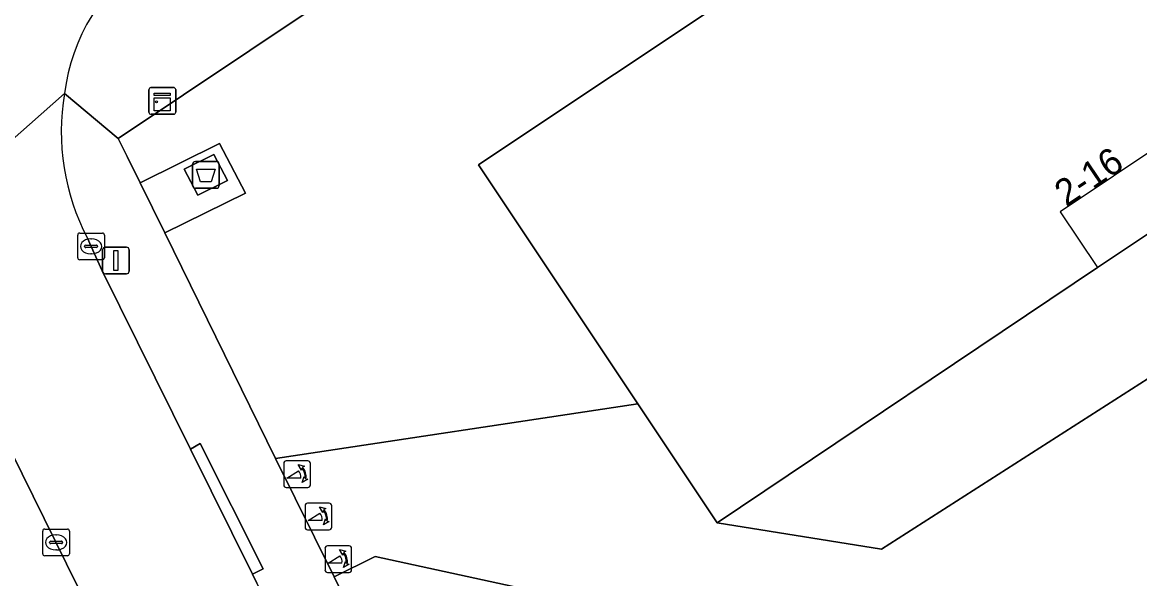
# Model space of a CAD drawing. Extents: x 161347 to 161881, y 382161 to 382804.
# Drawn here: x 161431.99 to 161473.77, y 382484.21 to 382505.01 of the extents above; entities that cross this region are included whole.
import ezdxf

# ---------------------------------------------------------------- set-up
doc = ezdxf.new("R2010")
doc.units = 0
for name, color, linetype in [('IMGEO_Afval_apart_plaats', 7, 'Continuous'), ('IMGEO_Erf', 7, 'Continuous'), ('IMGEO_Groenvoorziening', 7, 'Continuous'), ('IMGEO_Kast', 7, 'Continuous'), ('IMGEO_Kolk', 7, 'Continuous'), ('IMGEO_Lichtmast', 7, 'Continuous'), ('IMGEO_Pand', 7, 'Continuous'), ('IMGEO_Pand_nummerreeks', 7, 'Continuous'), ('IMGEO_Pand_overbouw', 7, 'Continuous'), ('IMGEO_Poller', 7, 'Continuous'), ('IMGEO_Rijbaan_lokaal_open', 7, 'Continuous'), ('IMGEO_Voetpad_gesloten', 7, 'Continuous'), ('IMGEO_Voetpad_open', 7, 'Continuous')]:
    doc.layers.add(name, color=color, linetype=linetype)

msp = doc.modelspace()

# ---------------------------------------------------------------- linework, layer by layer
at = {"layer": 'IMGEO_Afval_apart_plaats'}
for p, q in [((161438.356, 382498.913), (161438.356, 382499.713)), ((161438.356, 382499.713), (161438.356, 382498.913)), ((161438.456, 382499.813), (161439.246, 382499.813)), ((161439.246, 382499.813), (161438.456, 382499.813)), ((161439.346, 382499.713), (161439.346, 382498.913)), ((161439.346, 382498.913), (161439.346, 382499.713)), ((161439.246, 382498.813), (161438.456, 382498.813)), ((161438.456, 382498.813), (161439.246, 382498.813))]:
    msp.add_line(p, q, dxfattribs=at)
msp.add_lwpolyline([(161438.499, 382499.527), (161439.203, 382499.527), (161439.054, 382499.057), (161438.648, 382499.057), (161438.499, 382499.527)], dxfattribs=at)
for centre, start, end in [((161438.456, 382499.713), 90, 180), ((161438.456, 382499.713), 90, 180), ((161439.246, 382499.713), 0, 90), ((161439.246, 382499.713), 360, 90), ((161438.456, 382498.913), 180, 270), ((161438.456, 382498.913), 180, 270), ((161439.246, 382498.913), 270, 0), ((161439.246, 382498.913), 270, 0)]:
    msp.add_arc(centre, 0.1, start, end, dxfattribs=at)
at = {"layer": 'IMGEO_Erf'}
for points in [[(161490.393, 382508.028), (161478.402, 382500), (161475.671, 382498.172), (161472.197, 382495.844), (161457.968, 382486.306), (161464.119, 382485.318), (161475.341, 382492.496), (161486.569, 382500), (161491.524, 382503.311), (161494.163, 382503.857), (161500, 382502.6), (161512.072, 382500), (161520.272, 382498.234), (161522.532, 382496.667), (161539.309, 382469.447), (161545.974, 382467.342), (161536.968, 382481.919), (161534.501, 382485.913), (161525.798, 382500), (161525.522, 382500.446), (161522.985, 382502.254), (161514.037, 382504.398), (161513.736, 382503.008), (161502.162, 382505.515)], [(161529.133, 382472.859), (161500, 382479.131), (161475.815, 382484.338), (161475.174, 382481.282), (161481.945, 382479.796), (161482.684, 382479.645), (161485.462, 382479.04), (161497.294, 382476.49), (161493.615, 382459.469), (161478.517, 382462.719), (161477.639, 382458.64), (161456.073, 382463.283), (161459.231, 382477.951), (161480.549, 382473.354), (161481.379, 382477.176), (161445.186, 382485.044), (161443.651, 382484.283), (161457.359, 382456.669), (161460.674, 382449.996)]]:
    msp.add_lwpolyline(points, dxfattribs=at)
at = {"layer": 'IMGEO_Groenvoorziening'}
msp.add_lwpolyline([(161489.707, 382536.855), (161435.571, 382500.672), (161435.902, 382500), (161436.388, 382499.018), (161439.358, 382500.48), (161440.335, 382498.631), (161437.311, 382497.143), (161441.46, 382488.708), (161455.008, 382490.746), (161449.044, 382499.691), (161449.506, 382500), (161463.38, 382509.249)], dxfattribs=at)
at = {"layer": 'IMGEO_Kast'}
for p, q in [((161436.796, 382502.577), (161437.637, 382502.577)), ((161437.637, 382502.577), (161436.796, 382502.577)), ((161436.721, 382501.652), (161436.721, 382502.493)), ((161436.721, 382502.493), (161436.721, 382501.652)), ((161437.721, 382502.502), (161437.721, 382501.661)), ((161437.721, 382501.661), (161437.721, 382502.502)), ((161437.646, 382501.577), (161436.805, 382501.577)), ((161436.805, 382501.577), (161437.646, 382501.577))]:
    msp.add_line(p, q, dxfattribs=at)
for points in [[(161436.916, 382502.367), (161437.516, 382502.367), (161437.516, 382502.282), (161436.916, 382502.282), (161436.916, 382502.367)], [(161436.916, 382502.192), (161437.516, 382502.192), (161437.516, 382501.703), (161436.916, 382501.703), (161436.916, 382502.192)]]:
    msp.add_lwpolyline(points, dxfattribs=at)
msp.add_circle((161437, 382502.041), 0.0377, dxfattribs=at)
for centre, start, end in [((161436.799, 382502.499), 92.4484, 184.2845), ((161436.799, 382502.499), 92.4484, 184.2845), ((161437.643, 382502.499), 2.4484, 94.2845), ((161437.643, 382502.499), 2.4484, 94.2845), ((161436.799, 382501.655), 182.4484, 274.2845), ((161436.799, 382501.655), 182.4484, 274.2845), ((161437.643, 382501.655), 272.4484, 4.2845), ((161437.643, 382501.655), 272.4484, 4.2845)]:
    msp.add_arc(centre, 0.0779, start, end, dxfattribs=at)
at = {"layer": 'IMGEO_Kolk'}
for p, q in [((161434.131, 382497.137), (161434.983, 382497.137)), ((161434.056, 382496.211), (161434.056, 382497.063)), ((161434.358, 382496.68), (161434.756, 382496.68)), ((161434.544, 382496.917), (161434.569, 382496.917)), ((161435.057, 382497.063), (161435.057, 382496.211)), ((161434.315, 382496.631), (161434.315, 382496.643)), ((161434.753, 382496.594), (161434.355, 382496.594)), ((161434.567, 382496.357), (161434.542, 382496.357)), ((161434.799, 382496.643), (161434.799, 382496.631)), ((161434.983, 382496.137), (161434.131, 382496.137)), ((161432.748, 382485.142), (161432.748, 382485.994)), ((161432.823, 382486.068), (161433.675, 382486.068)), ((161433.236, 382485.848), (161433.261, 382485.848)), ((161433.749, 382485.994), (161433.749, 382485.142)), ((161433.007, 382485.562), (161433.007, 382485.574)), ((161433.445, 382485.525), (161433.047, 382485.525)), ((161433.05, 382485.611), (161433.448, 382485.611)), ((161433.491, 382485.574), (161433.491, 382485.562)), ((161433.675, 382485.068), (161432.823, 382485.068)), ((161433.259, 382485.288), (161433.234, 382485.288))]:
    msp.add_line(p, q, dxfattribs=at)
for points in [[(161434.131, 382497.137), (161434.983, 382497.137)], [(161434.056, 382496.211), (161434.056, 382497.063)], [(161435.057, 382497.063), (161435.057, 382496.211)], [(161434.983, 382496.137), (161434.131, 382496.137)], [(161432.748, 382485.142), (161432.748, 382485.994)], [(161432.823, 382486.068), (161433.675, 382486.068)], [(161433.749, 382485.994), (161433.749, 382485.142)], [(161433.675, 382485.068), (161432.823, 382485.068)]]:
    msp.add_lwpolyline(points, dxfattribs=at)
for centre, radius, start, end in [((161434.133, 382497.061), 0.0765, 91.552, 178.448), ((161434.133, 382497.061), 0.0765, 91.552, 178.448), ((161434.981, 382497.061), 0.0765, 1.552, 88.448), ((161434.981, 382497.061), 0.0765, 1.552, 88.448), ((161434.355, 382496.64), 0.0403, 85.8775, 175.7526), ((161434.76, 382496.642), 0.0386, 1.7309, 96.639), ((161434.352, 382496.63), 0.0366, 178.938, 274.7102), ((161434.756, 382496.637), 0.043, 264.8664, 352.4533), ((161434.133, 382496.213), 0.0765, 181.552, 268.448), ((161434.133, 382496.213), 0.0765, 181.552, 268.448), ((161434.981, 382496.213), 0.0765, 271.552, 358.448), ((161434.981, 382496.213), 0.0765, 271.552, 358.448), ((161432.825, 382485.992), 0.0765, 91.552, 178.448), ((161432.825, 382485.992), 0.0765, 91.552, 178.448), ((161433.673, 382485.992), 0.0765, 1.552, 88.448), ((161433.673, 382485.992), 0.0765, 1.552, 88.448), ((161433.047, 382485.571), 0.0403, 85.8775, 175.7526), ((161433.044, 382485.561), 0.0366, 178.938, 274.7102), ((161433.448, 382485.568), 0.043, 264.8664, 352.4533), ((161433.452, 382485.573), 0.0386, 1.7309, 96.639), ((161432.825, 382485.144), 0.0765, 181.552, 268.448), ((161432.825, 382485.144), 0.0765, 181.552, 268.448), ((161433.673, 382485.144), 0.0765, 271.552, 358.448), ((161433.673, 382485.144), 0.0765, 271.552, 358.448)]:
    msp.add_arc(centre, radius, start, end, dxfattribs=at)
for centre, major_axis, ratio, start_param, end_param in [((161434.543, 382496.637), (-0.387, 0.002), 0.722429, 4.712389, 7.853982), ((161434.568, 382496.637), (-0.39, 0.002), 0.717154, 1.570796, 4.712389), ((161433.235, 382485.568), (-0.387, 0.002), 0.722429, 4.712389, 7.853982), ((161433.26, 382485.568), (-0.39, 0.002), 0.717154, 1.570796, 4.712389)]:
    msp.add_ellipse(centre, major_axis=major_axis, ratio=ratio, start_param=start_param, end_param=end_param, dxfattribs=at)
at = {"layer": 'IMGEO_Lichtmast'}
for p, q in [((161434.99, 382495.71), (161434.99, 382496.51)), ((161434.99, 382496.51), (161434.99, 382495.71)), ((161435.09, 382496.61), (161435.88, 382496.61)), ((161435.88, 382496.61), (161435.09, 382496.61)), ((161435.98, 382496.51), (161435.98, 382495.71)), ((161435.98, 382495.71), (161435.98, 382496.51)), ((161435.88, 382495.61), (161435.09, 382495.61)), ((161435.09, 382495.61), (161435.88, 382495.61))]:
    msp.add_line(p, q, dxfattribs=at)
msp.add_lwpolyline([(161435.41, 382496.485), (161435.56, 382496.485), (161435.56, 382495.735), (161435.41, 382495.735), (161435.41, 382496.485)], dxfattribs=at)
for centre, start, end in [((161435.09, 382496.51), 90, 180), ((161435.09, 382496.51), 90, 180), ((161435.88, 382496.51), 0, 90), ((161435.88, 382496.51), 360, 90), ((161435.09, 382495.71), 180, 270), ((161435.09, 382495.71), 180, 270), ((161435.88, 382495.71), 270, 0), ((161435.88, 382495.71), 270, 0)]:
    msp.add_arc(centre, 0.1, start, end, dxfattribs=at)
at = {"layer": 'IMGEO_Pand'}
msp.add_lwpolyline([(161463.38, 382509.249), (161449.506, 382500), (161449.044, 382499.691), (161455.008, 382490.746), (161457.968, 382486.306), (161472.197, 382495.844), (161475.671, 382498.172), (161478.402, 382500), (161490.393, 382508.028)], dxfattribs=at)
at = {"layer": 'IMGEO_Pand_overbouw'}
msp.add_lwpolyline([(161474.826, 382500.62), (161470.803, 382497.924), (161472.197, 382495.844), (161475.671, 382498.172), (161476.221, 382498.54)], close=True, dxfattribs=at)
at = {"layer": 'IMGEO_Poller'}
for p, q in [((161441.762, 382488.525), (161441.762, 382487.718)), ((161441.762, 382488.525), (161441.762, 382487.718)), ((161442.664, 382488.62), (161441.856, 382488.62)), ((161442.664, 382488.62), (161441.856, 382488.62)), ((161442.758, 382487.718), (161442.758, 382488.525)), ((161442.758, 382487.718), (161442.758, 382488.525)), ((161441.856, 382487.623), (161442.664, 382487.623)), ((161441.856, 382487.623), (161442.664, 382487.623)), ((161442.56, 382486.942), (161442.56, 382486.135)), ((161442.56, 382486.942), (161442.56, 382486.135)), ((161443.462, 382487.037), (161442.654, 382487.037)), ((161443.462, 382487.037), (161442.654, 382487.037)), ((161443.556, 382486.135), (161443.556, 382486.942)), ((161443.556, 382486.135), (161443.556, 382486.942)), ((161442.654, 382486.04), (161443.462, 382486.04)), ((161442.654, 382486.04), (161443.462, 382486.04)), ((161444.208, 382485.441), (161443.4, 382485.441)), ((161444.208, 382485.441), (161443.4, 382485.441)), ((161443.306, 382485.346), (161443.306, 382484.539)), ((161443.306, 382485.346), (161443.306, 382484.539)), ((161444.302, 382484.539), (161444.302, 382485.346)), ((161444.302, 382484.539), (161444.302, 382485.346)), ((161443.4, 382484.444), (161444.208, 382484.444)), ((161443.4, 382484.444), (161444.208, 382484.444))]:
    msp.add_line(p, q, dxfattribs=at)
for points in [[(161442.441, 382488.349), (161442.429, 382488.276), (161442.304, 382488.481)], [(161442.304, 382488.481), (161442.535, 382488.415), (161442.464, 382488.383)], [(161442.397, 382487.976), (161441.884, 382487.976), (161442.314, 382488.251)], [(161442.457, 382487.804), (161442.523, 382488.035), (161442.553, 382487.967)], [(161442.589, 382487.94), (161442.661, 382487.929), (161442.457, 382487.804)], [(161443.195, 382486.393), (161442.682, 382486.393), (161443.112, 382486.668)], [(161443.239, 382486.766), (161443.227, 382486.693), (161443.102, 382486.898)], [(161443.102, 382486.898), (161443.333, 382486.832), (161443.262, 382486.8)], [(161443.255, 382486.221), (161443.321, 382486.452), (161443.351, 382486.384)], [(161443.387, 382486.357), (161443.459, 382486.346), (161443.255, 382486.221)], [(161443.941, 382484.797), (161443.428, 382484.797), (161443.858, 382485.072)], [(161443.985, 382485.17), (161443.973, 382485.097), (161443.848, 382485.302)], [(161443.848, 382485.302), (161444.079, 382485.236), (161444.008, 382485.204)], [(161444.001, 382484.625), (161444.067, 382484.856), (161444.097, 382484.788)], [(161444.133, 382484.761), (161444.205, 382484.75), (161444.001, 382484.625)]]:
    msp.add_lwpolyline(points, dxfattribs=at)
for centre, radius, start, end in [((161441.856, 382488.525), 0.0946, 90, 180), ((161441.856, 382488.525), 0.0946, 90, 180), ((161442.083, 382488.036), 0.476, 351.7527, 41.1691), ((161442.083, 382488.036), 0.516, 349.3569, 42.2912), ((161442.664, 382488.525), 0.0946, 0, 90), ((161442.664, 382488.525), 0.0946, 0, 90), ((161442.069, 382488.026), 0.332, 351.3247, 42.4854), ((161441.856, 382487.718), 0.0946, 180, 270), ((161441.856, 382487.718), 0.0946, 180, 270), ((161442.664, 382487.718), 0.0946, 270, 0), ((161442.664, 382487.718), 0.0946, 270, 0), ((161442.654, 382486.942), 0.0946, 90, 180), ((161442.654, 382486.942), 0.0946, 90, 180), ((161442.867, 382486.443), 0.332, 351.3247, 42.4854), ((161442.881, 382486.453), 0.476, 351.7527, 41.1691), ((161442.881, 382486.453), 0.516, 349.3569, 42.2912), ((161443.462, 382486.942), 0.0946, 0, 90), ((161443.462, 382486.942), 0.0946, 0, 90), ((161442.654, 382486.135), 0.0946, 180, 270), ((161442.654, 382486.135), 0.0946, 180, 270), ((161443.462, 382486.135), 0.0946, 270, 0), ((161443.462, 382486.135), 0.0946, 270, 0), ((161443.4, 382485.346), 0.0946, 90, 180), ((161443.4, 382485.346), 0.0946, 90, 180), ((161444.208, 382485.346), 0.0946, 0, 90), ((161444.208, 382485.346), 0.0946, 0, 90), ((161443.613, 382484.847), 0.332, 351.3247, 42.4854), ((161443.627, 382484.857), 0.476, 351.7527, 41.1691), ((161443.627, 382484.857), 0.516, 349.3569, 42.2912), ((161443.4, 382484.539), 0.0946, 180, 270), ((161443.4, 382484.539), 0.0946, 180, 270), ((161444.208, 382484.539), 0.0946, 270, 0), ((161444.208, 382484.539), 0.0946, 270, 0)]:
    msp.add_arc(centre, radius, start, end, dxfattribs=at)
at = {"layer": 'IMGEO_Rijbaan_lokaal_open'}
for points in [[(161427.664, 382497.144), (161433.561, 382502.355)], [(161433.561, 382502.355), (161427.664, 382497.144)], [(161480.29, 382392.675), (161478.84, 382407.183), (161477.805, 382409.341), (161477.113, 382410.786), (161463.455, 382438.086), (161463.358, 382438.279), (161462.466, 382440.119), (161462.329, 382440.433), (161458.175, 382448.856), (161457.689, 382449.818), (161441.548, 382482.463), (161440.761, 382484.044), (161440.593, 382484.384), (161438.28, 382489.057), (161434.967, 382495.723), (161434.557, 382496.637), (161434.422, 382496.948)], [(161428.143, 382496.121), (161429.484, 382493.169), (161432.808, 382486.467), (161436.553, 382478.847), (161440.593, 382470.696), (161444.732, 382462.271), (161445.063, 382461.614), (161447.12, 382457.484), (161452.227, 382447.149), (161456.306, 382438.986), (161456.426, 382438.783), (161461.114, 382429.288), (161465.21, 382421.123), (161469.744, 382412.024), (161471.751, 382407.93), (161472.321, 382406.713)]]:
    msp.add_lwpolyline(points, dxfattribs=at)
for centre, radius, start, end in [((161440.845, 382501.431), 7.342, 124.3015, 172.7699), ((161441.952, 382500.919), 8.513, 170.2889, 207.8065)]:
    msp.add_arc(centre, radius, start, end, dxfattribs=at)
at = {"layer": 'IMGEO_Voetpad_gesloten'}
msp.add_lwpolyline([(161439.146, 382500.072), (161438.04, 382499.528), (161438.555, 382498.554), (161439.661, 382499.098)], close=True, dxfattribs=at)
at = {"layer": 'IMGEO_Voetpad_open'}
for points in [[(161433.561, 382502.355), (161435.571, 382500.672), (161489.707, 382536.855)], [(161512.072, 382500), (161500, 382502.6), (161494.163, 382503.857), (161491.524, 382503.311), (161486.569, 382500), (161475.341, 382492.496), (161464.119, 382485.318), (161457.968, 382486.306), (161455.008, 382490.746), (161441.46, 382488.708), (161443.651, 382484.283), (161445.186, 382485.044), (161481.379, 382477.176), (161481.813, 382479.147), (161481.945, 382479.796), (161475.174, 382481.282), (161475.815, 382484.338), (161500, 382479.131), (161529.133, 382472.859)], [(161437.311, 382497.143), (161436.388, 382499.018), (161435.902, 382500), (161435.571, 382500.672), (161433.561, 382502.355)], [(161457.689, 382449.818), (161458.175, 382448.856), (161460.674, 382449.996), (161457.359, 382456.669), (161443.651, 382484.283), (161441.46, 382488.708), (161437.311, 382497.143)], [(161434.422, 382496.948), (161434.557, 382496.637), (161434.967, 382495.723), (161438.28, 382489.057), (161438.635, 382489.271), (161440.999, 382484.582), (161440.593, 382484.384), (161440.761, 382484.044)], [(161447.12, 382457.484), (161446.673, 382457.262), (161444.616, 382461.392), (161445.063, 382461.614), (161444.732, 382462.271), (161440.593, 382470.696), (161440.146, 382470.474), (161436.106, 382478.625), (161436.553, 382478.847), (161432.808, 382486.467), (161429.484, 382493.169), (161428.143, 382496.121)]]:
    msp.add_lwpolyline(points, dxfattribs=at)
for points in [[(161437.311, 382497.143), (161440.335, 382498.631), (161439.358, 382500.48), (161436.388, 382499.018)], [(161438.555, 382498.554), (161438.04, 382499.528), (161439.146, 382500.072), (161439.661, 382499.098)], [(161440.593, 382484.384), (161440.999, 382484.582), (161438.635, 382489.271), (161438.28, 382489.057)]]:
    msp.add_lwpolyline(points, close=True, dxfattribs=at)
for centre, radius, start, end in [((161440.845, 382501.431), 7.342, 124.3015, 172.7699), ((161441.952, 382500.919), 8.513, 170.2889, 207.8065)]:
    msp.add_arc(centre, radius, start, end, dxfattribs=at)

# ---------------------------------------------------------------- texts
at = {"layer": 'IMGEO_Pand_nummerreeks'}
msp.add_text('2-16', height=1, rotation=33.816, dxfattribs=at).set_placement((161471.031, 382498.09))

doc.saveas('drawing.dxf')
